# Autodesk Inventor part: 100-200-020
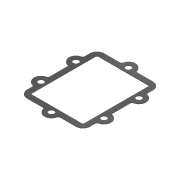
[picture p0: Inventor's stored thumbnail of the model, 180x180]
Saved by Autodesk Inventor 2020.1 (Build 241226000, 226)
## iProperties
Created: 2010-02
Part Number: 100-200-020
Material: Kauczuk
Document SubType Name: Modeling
Designer: F.Stasiak
Mass: 24.9018 g
Surface Area: 304.867 cm^2
Volume: 26.7761 cm^3
Density: 0.93 g/cm^3
Appearance: Kauczuk - czarny - wersja 1.1
Manager: www.cadconsulting.pl
Company: Fabian Stasiak CAD Consulting
Author: F.Stasiak
Subject: Zbiór ćwiczeń. Autodesk Inventor 2020. Kurs podstawowy
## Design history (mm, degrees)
sketch "Szkic1"
  geometry: L1 (75, 200)-(75, 20); L2 (70, 15)-(-70, 15); L3 (-75, 20)-(-75, 200); L4 (-70, 205)-(70, 205); L5 (-70, 220)-(-24.495, 220); L6 (-90, 184.495)-(-90, 200); L7 (-90, 84.495)-(-90, 135.505); L8 (-90, 20)-(-90, 35.505); L9 (-24.495, 0)-(-70, 0); L10 (70, 0)-(24.495, 0); L11 (90, 35.505)-(90, 20); L12 (90, 135.505)-(90, 84.495); L13 (90, 200)-(90, 184.495); L14 (24.495, 220)-(70, 220); C1 r 8 at (-90, 160); C2 r 8 at (-90, 60); C3 r 8 at (0, 0); C4 r 8 at (90, 60); C5 r 8 at (90, 160); C6 r 8 at (0, 220); A1 r 5 centre (70, 200) between (75, 200) and (70, 205); A2 r 5 centre (70, 20) between (70, 15) and (75, 20); A3 r 5 centre (-70, 20) between (-75, 20) and (-70, 15); A4 r 5 centre (-70, 200) between (-70, 205) and (-75, 200); A5 r 20 centre (-70, 200) between (-70, 220) and (-90, 200); A6 r 5 centre (-95, 184.495) between (-94, 179.596) and (-90, 184.495); A7 r 20 centre (-90, 160) between (-94, 179.596) and (-94, 140.404); A8 r 5 centre (-95, 135.505) between (-90, 135.505) and (-94, 140.404); A9 r 5 centre (-95, 84.495) between (-94, 79.596) and (-90, 84.495); A10 r 20 centre (-90, 60) between (-94, 79.596) and (-94, 40.404); A11 r 5 centre (-95, 35.505) between (-90, 35.505) and (-94, 40.404); A12 r 20 centre (-70, 20) between (-90, 20) and (-70, 0); A13 r 5 centre (-24.495, -5) between (-19.596, -4) and (-24.495, 0); A14 r 20 centre (0, 0) between (-19.596, -4) and (19.596, -4); A15 r 5 centre (24.495, -5) between (24.495, 0) and (19.596, -4); A16 r 20 centre (70, 20) between (70, 0) and (90, 20); A17 r 5 centre (95, 35.505) between (94, 40.404) and (90, 35.505); A18 r 20 centre (90, 60) between (94, 40.404) and (94, 79.596); A19 r 5 centre (95, 84.495) between (90, 84.495) and (94, 79.596); A20 r 5 centre (95, 135.505) between (94, 140.404) and (90, 135.505); A21 r 20 centre (90, 160) between (94, 140.404) and (94, 179.596); A22 r 5 centre (95, 184.495) between (90, 184.495) and (94, 179.596); A23 r 20 centre (70, 200) between (90, 200) and (70, 220); A24 r 5 centre (24.495, 225) between (19.596, 224) and (24.495, 220); A25 r 20 centre (0, 220) between (19.596, 224) and (-19.596, 224); A26 r 5 centre (-24.495, 225) between (-24.495, 220) and (-19.596, 224); 1 further point
  constraints: 52 point on circle, 32 centre point, 28 end point, 5 equal radius
  dimensions: "d0" = 16 diameter of C6
extrude "Wyciągnięcie proste1" new body sketch "Szkic1" distance "d1" = 2; taper "d2" = 0 deg
node "Bryła1"
other parameters: "d22" = 0, "d23" = 0, "d24" = 0, "d25" = 0, "d26" = 0, "d27" = 0
